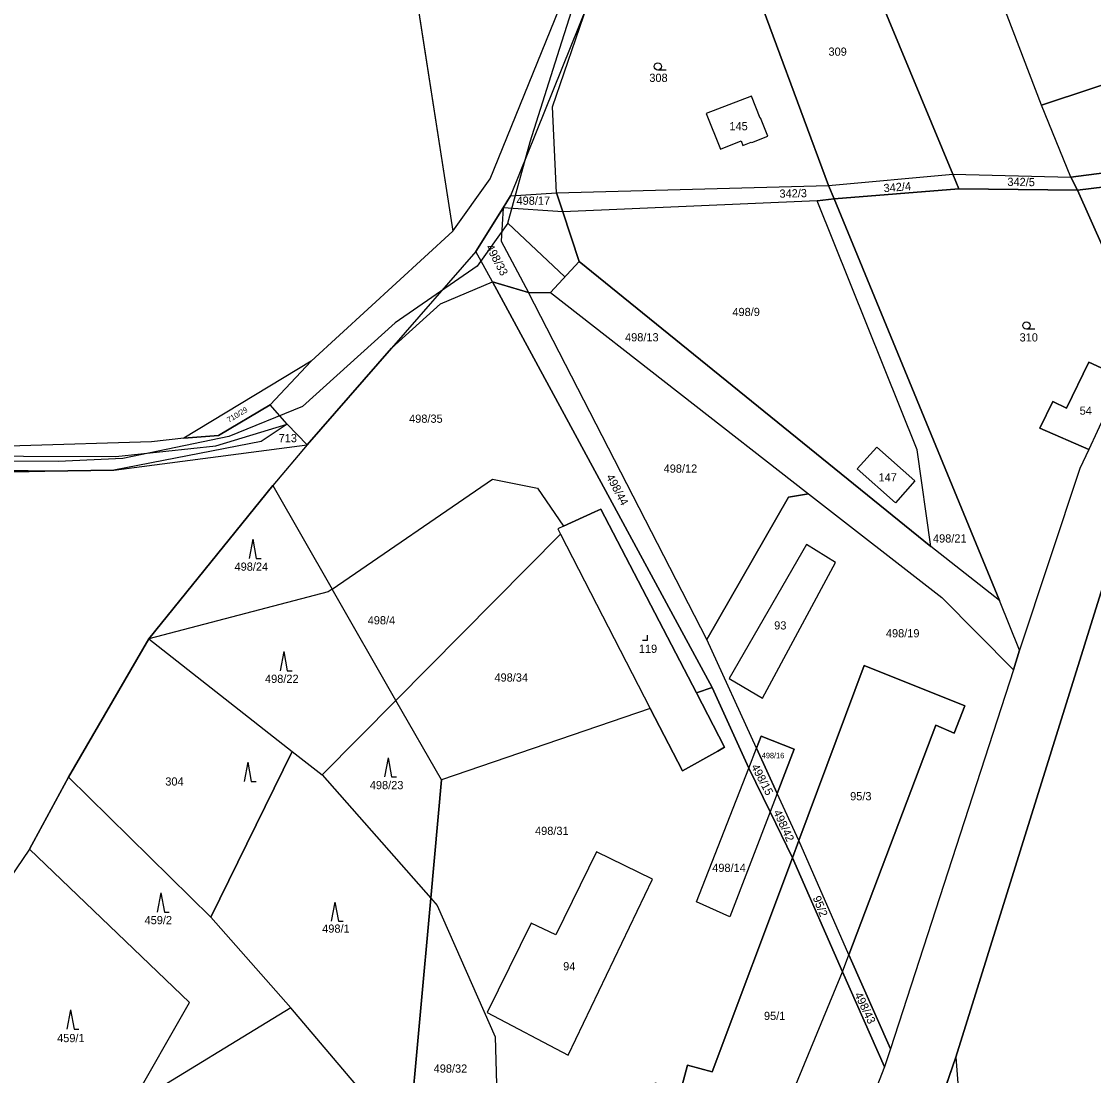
# Model space of a CAD drawing. Extents: x -590606 to -587796, y -1065936 to -1062515.
# Drawn here: x -589413.2 to -589191, y -1064752.6 to -1064534.1 of the extents above; entities that cross this region are included whole.
import ezdxf

# ---------------------------------------------------------------- set-up
doc = ezdxf.new("R2010")
doc.units = 0
for name, color, linetype in [('Cesty', 7, 'Continuous'), ('Parcela nároku', 7, 'Continuous'), ('Vnější obvod_ Studené', 7, 'Continuous'), ('Vrstva 30', 7, 'Continuous')]:
    doc.layers.add(name, color=color, linetype=linetype)

msp = doc.modelspace()

# ---------------------------------------------------------------- linework, layer by layer
at = {"layer": 'Cesty'}
for points in [[(-589300.58, -1064587.06), (-589312.39, -1064575.92), (-589307.76, -1064559.09), (-589301.66, -1064539.86), (-589293.47, -1064514.04), (-589288.03, -1064490.09), (-589285.92, -1064475.12)], [(-589312.39, -1064575.92), (-589318.72, -1064584.83), (-589335.76, -1064596.6), (-589354.95, -1064613.9), (-589370.21, -1064620.11), (-589392.14, -1064624.65), (-589405.6, -1064625.31), (-589467.35, -1064625.2), (-589485.5, -1064624.04), (-589517.23, -1064616.87), (-589543.56, -1064607.17), (-589549.94, -1064607.84), (-589566.34, -1064608.24), (-589595.98, -1064606.38), (-589632.73, -1064602.69), (-589650.77, -1064600.08), (-589699.72, -1064596.26), (-589711.59, -1064596.2), (-589764.62, -1064605.69), (-589799.36, -1064611.91)]]:
    msp.add_lwpolyline(points, dxfattribs=at)
at = {"layer": 'Parcela nároku'}
for points in [[(-589417.38, -1064171.67), (-589379.94, -1064201.41), (-589369.57, -1064272.3), (-589363.57, -1064313.27), (-589352.69, -1064387.69), (-589339.13, -1064479.06), (-589323.75, -1064577.55), (-589353.13, -1064604.54), (-589379.5, -1064620.44), (-589386.23, -1064621.24), (-589413.51, -1064622.05)], [(-589295.88, -1064530.66), (-589311.85, -1064570.25), (-589313.34, -1064572.76), (-589319, -1064581.76), (-589353.94, -1064621.82), (-589358.1, -1064617.56), (-589361.6, -1064613.55), (-589353.13, -1064604.54), (-589323.75, -1064577.55), (-589316.02, -1064566.74), (-589296.44, -1064518.34)], [(-589185.08, -1064607.88), (-589192.01, -1064622.83), (-589193.83, -1064626.75), (-589206.34, -1064664.38), (-589207.6, -1064668.51), (-589233.09, -1064747.06), (-589234.34, -1064750.74), (-589263.43, -1064825.24)], [(-589228.83, -1064775.58), (-589219.53, -1064748.72), (-589186.36, -1064642.57)], [(-589276.55, -1064755.62), (-589275.16, -1064750.39), (-589270.07, -1064751.82), (-589253.42, -1064707.43), (-589258.04, -1064697.93), (-589266.37, -1064719.64), (-589273.27, -1064716.55), (-589262.46, -1064688.85), (-589270.04, -1064672.11), (-589273.31, -1064673.23), (-589267.45, -1064684.51), (-589268.88, -1064685.31), (-589276.21, -1064689.44), (-589282.87, -1064676.49), (-589326.15, -1064691.27), (-589328.36, -1064715.8), (-589327.02, -1064717.33), (-589315.01, -1064744.55), (-589314.53, -1064761.77)]]:
    msp.add_lwpolyline(points, dxfattribs=at)
for points in [[(-589232.4, -1064471.45), (-589208.79, -1064446.47), (-589168.83, -1064517.27), (-589164.65, -1064524.67), (-589161.07, -1064530.98), (-589156.51, -1064536.45), (-589159.83, -1064537.55), (-589201.82, -1064551.44)], [(-589201.82, -1064551.44), (-589232.4, -1064471.45), (-589251.47, -1064490.39), (-589220.15, -1064565.79), (-589195.69, -1064566.38)], [(-589290.65, -1064472.89), (-589339.13, -1064479.06), (-589323.75, -1064577.55), (-589316.02, -1064566.74), (-589296.44, -1064518.34), (-589290.27, -1064497.32), (-589287.86, -1064475.38)], [(-589251.47, -1064490.39), (-589268.87, -1064506.17), (-589245.96, -1064568.09), (-589220.15, -1064565.79)], [(-589245.96, -1064568.09), (-589268.87, -1064506.17), (-589295.88, -1064530.66), (-589311.85, -1064570.25), (-589302.27, -1064569.61)], [(-589201.82, -1064551.44), (-589159.83, -1064537.55), (-589146.1, -1064555.02), (-589143.75, -1064552.4), (-589146.65, -1064555.73), (-589171.28, -1064563.22), (-589195.69, -1064566.38)], [(-589271.26, -1064553.15), (-589268.32, -1064560.56), (-589264.03, -1064558.88), (-589263.66, -1064559.83), (-589261.92, -1064559.12), (-589261.85, -1064559.21), (-589258.52, -1064557.86), (-589259.99, -1064554.08), (-589260.11, -1064554.14), (-589261.9, -1064549.56)], [(-589258.52, -1064557.86), (-589259.99, -1064554.08), (-589260.11, -1064554.14), (-589261.9, -1064549.56), (-589271.26, -1064553.15), (-589268.32, -1064560.56), (-589264.03, -1064558.88), (-589263.66, -1064559.83), (-589261.92, -1064559.12), (-589261.85, -1064559.21)], [(-589171.28, -1064563.22), (-589146.65, -1064555.73), (-589149.4, -1064559.72), (-589171.12, -1064566.23), (-589194.33, -1064569.05), (-589195.69, -1064566.38)], [(-589171.12, -1064566.23), (-589149.4, -1064559.72), (-589167.86, -1064579.14), (-589170.85, -1064576.72), (-589177.93, -1064571.33), (-589181.12, -1064575.26), (-589183.77, -1064573.16), (-589186.71, -1064576.96), (-589184.14, -1064578.99), (-589185.99, -1064581.28), (-589179.04, -1064586.54), (-589174.88, -1064589.8), (-589180.97, -1064599.01), (-589194.33, -1064569.05)], [(-589245.96, -1064568.09), (-589220.15, -1064565.79), (-589218.91, -1064568.78), (-589244.72, -1064570.89)], [(-589220.15, -1064565.79), (-589195.69, -1064566.38), (-589194.33, -1064569.05), (-589218.91, -1064568.78)], [(-589302.27, -1064569.61), (-589300.98, -1064573.57), (-589313.34, -1064572.76), (-589311.85, -1064570.25)], [(-589245.96, -1064568.09), (-589244.72, -1064570.89), (-589248.26, -1064571.29), (-589300.98, -1064573.57), (-589302.27, -1064569.61)], [(-589194.33, -1064569.05), (-589180.97, -1064599.01), (-589185.08, -1064607.88), (-589191.95, -1064604.69), (-589196.61, -1064614.26), (-589199.45, -1064612.86), (-589202.15, -1064618.39), (-589192.01, -1064622.83), (-589193.83, -1064626.75), (-589206.34, -1064664.38), (-589210.5, -1064654.09), (-589244.72, -1064570.89), (-589218.91, -1064568.78)], [(-589248.26, -1064571.29), (-589300.98, -1064573.57), (-589297.58, -1064583.86), (-589224.75, -1064642.9), (-589227.54, -1064622.88)], [(-589244.72, -1064570.89), (-589210.5, -1064654.09), (-589224.75, -1064642.9), (-589227.54, -1064622.88), (-589248.26, -1064571.29)], [(-589319, -1064581.76), (-589313.34, -1064572.76), (-589313.79, -1064579.63), (-589308.1, -1064590.25), (-589315.59, -1064588.05)], [(-589300.98, -1064573.57), (-589313.34, -1064572.76), (-589313.79, -1064579.63), (-589308.1, -1064590.25), (-589303.57, -1064590.25), (-589250.07, -1064631.99), (-589222.47, -1064653.52), (-589207.6, -1064668.51), (-589206.34, -1064664.38), (-589210.5, -1064654.09), (-589224.75, -1064642.9), (-589297.58, -1064583.86)], [(-589315.59, -1064588.05), (-589319, -1064581.76), (-589353.94, -1064621.82), (-589361.07, -1064630.25), (-589348.76, -1064651.76), (-589315.53, -1064628.94), (-589306.24, -1064630.8), (-589300.86, -1064638.73), (-589294.32, -1064635.71), (-589293.1, -1064635.15), (-589273.31, -1064673.23), (-589270.04, -1064672.11)], [(-589308.1, -1064590.25), (-589315.59, -1064588.05), (-589270.04, -1064672.11), (-589262.46, -1064688.85), (-589260.85, -1064684.74), (-589271.17, -1064662.21)], [(-589303.57, -1064590.25), (-589250.07, -1064631.99), (-589254.19, -1064632.69), (-589271.17, -1064662.21), (-589308.1, -1064590.25)], [(-589358.1, -1064617.56), (-589361.6, -1064613.55), (-589372.34, -1064619.94), (-589379.5, -1064620.44), (-589386.23, -1064621.24), (-589413.51, -1064622.05), (-589457.96, -1064622.14), (-589477.97, -1064621.63), (-589499, -1064619.25), (-589523.88, -1064612.81), (-589541.19, -1064604.66), (-589542.09, -1064606.65), (-589525.32, -1064613.43), (-589500.34, -1064620.07), (-589470.25, -1064623.98), (-589393.65, -1064624.26), (-589372.9, -1064622.03)], [(-589353.13, -1064604.54), (-589379.5, -1064620.44), (-589372.34, -1064619.94), (-589361.6, -1064613.55)], [(-589202.15, -1064618.39), (-589199.45, -1064612.86), (-589196.61, -1064614.26), (-589191.95, -1064604.69), (-589185.08, -1064607.88), (-589192.01, -1064622.83)], [(-589393.65, -1064624.26), (-589372.9, -1064622.03), (-589358.1, -1064617.56), (-589363.47, -1064621.18), (-589394.04, -1064627.1), (-589408.35, -1064627.34), (-589467.25, -1064626.15), (-589500.72, -1064621.47), (-589504.92, -1064620.61), (-589508.23, -1064619.91), (-589524.33, -1064616.05), (-589543.01, -1064608.6), (-589542.09, -1064606.65), (-589525.32, -1064613.43), (-589500.34, -1064620.07), (-589470.25, -1064623.98)], [(-589358.1, -1064617.56), (-589363.47, -1064621.18), (-589394.04, -1064627.1), (-589353.94, -1064621.82)], [(-589500.84, -1064624.06), (-589472.75, -1064628.4), (-589408.35, -1064627.34), (-589394.04, -1064627.1), (-589353.94, -1064621.82), (-589361.07, -1064630.25), (-589386.79, -1064662.08), (-589403.44, -1064690.75), (-589411.5, -1064705.67), (-589425, -1064725.38), (-589447.12, -1064755.09), (-589470.54, -1064721.2), (-589496.13, -1064671.82), (-589500.39, -1064655.52), (-589501.22, -1064639.68)], [(-589500.72, -1064621.47), (-589467.25, -1064626.15), (-589408.35, -1064627.34), (-589472.75, -1064628.4), (-589500.84, -1064624.06)], [(-589232.05, -1064633.87), (-589240.02, -1064626.79), (-589235.94, -1064622.3), (-589228.01, -1064629.32)], [(-589235.94, -1064622.3), (-589228.01, -1064629.32), (-589232.05, -1064633.87), (-589240.02, -1064626.79)], [(-589315.53, -1064628.94), (-589306.24, -1064630.8), (-589300.86, -1064638.73), (-589302.01, -1064639.26), (-589301.45, -1064640.36), (-589335.56, -1064674.82), (-589348.76, -1064651.76)], [(-589386.79, -1064662.08), (-589361.07, -1064630.25), (-589348.76, -1064651.76), (-589349.58, -1064652.32)], [(-589222.47, -1064653.52), (-589207.6, -1064668.51), (-589233.09, -1064747.06), (-589241.68, -1064727.54), (-589223.69, -1064679.94), (-589219.9, -1064681.59), (-589217.69, -1064675.93), (-589238.57, -1064667.58), (-589252.09, -1064703.88), (-589256.57, -1064694.1), (-589253.04, -1064684.91), (-589259.88, -1064682.25), (-589260.85, -1064684.74), (-589271.17, -1064662.21), (-589254.19, -1064632.69), (-589250.07, -1064631.99)], [(-589294.32, -1064635.71), (-589300.86, -1064638.73), (-589302.01, -1064639.26), (-589301.45, -1064640.36), (-589282.87, -1064676.49), (-589276.21, -1064689.44), (-589268.88, -1064685.31), (-589267.45, -1064684.51), (-589273.31, -1064673.23), (-589293.1, -1064635.15)], [(-589301.45, -1064640.36), (-589282.87, -1064676.49), (-589326.15, -1064691.27), (-589335.56, -1064674.82)], [(-589250.46, -1064642.52), (-589266.51, -1064670.27), (-589259.59, -1064674.34), (-589244.49, -1064646.21)], [(-589266.51, -1064670.27), (-589259.59, -1064674.34), (-589244.49, -1064646.21), (-589250.46, -1064642.52)], [(-589123.59, -1064757.72), (-589141.72, -1064723.62), (-589157.85, -1064685.09), (-589185.23, -1064641.99), (-589186.36, -1064642.57), (-589219.53, -1064748.72), (-589218.27, -1064765.02), (-589213.92, -1064786.57), (-589188.45, -1064839.84), (-589159.82, -1064824.9), (-589138.93, -1064817.47), (-589090.35, -1064802), (-589107.58, -1064783.08)], [(-589335.56, -1064674.82), (-589348.76, -1064651.76), (-589349.58, -1064652.32), (-589386.79, -1064662.08), (-589357.1, -1064685.38), (-589350.86, -1064690.27)], [(-589403.44, -1064690.75), (-589386.79, -1064662.08), (-589357.1, -1064685.38), (-589373.96, -1064719.72)], [(-589252.09, -1064703.88), (-589238.57, -1064667.58), (-589217.69, -1064675.93), (-589219.9, -1064681.59), (-589223.69, -1064679.94), (-589241.68, -1064727.54)], [(-589326.15, -1064691.27), (-589335.56, -1064674.82), (-589350.86, -1064690.27), (-589328.36, -1064715.8)], [(-589259.88, -1064682.25), (-589253.04, -1064684.91), (-589256.57, -1064694.1), (-589260.85, -1064684.74)], [(-589262.46, -1064688.85), (-589260.85, -1064684.74), (-589256.57, -1064694.1), (-589258.04, -1064697.93)], [(-589350.86, -1064690.27), (-589328.36, -1064715.8), (-589332.88, -1064765.85), (-589343.1, -1064755.32), (-589357.37, -1064738.5), (-589373.96, -1064719.72), (-589357.1, -1064685.38)], [(-589273.27, -1064716.55), (-589262.46, -1064688.85), (-589258.04, -1064697.93), (-589266.37, -1064719.64)], [(-589390.57, -1064758.82), (-589378.38, -1064737.45), (-589411.5, -1064705.67), (-589403.44, -1064690.75), (-589373.96, -1064719.72), (-589357.37, -1064738.5)], [(-589256.57, -1064694.1), (-589258.04, -1064697.93), (-589253.42, -1064707.43), (-589252.09, -1064703.88)], [(-589252.09, -1064703.88), (-589253.42, -1064707.43), (-589243.01, -1064731.06), (-589241.68, -1064727.54)], [(-589378.38, -1064737.45), (-589411.5, -1064705.67), (-589425, -1064725.38), (-589416.09, -1064747.85), (-589424.1, -1064799.94), (-589411.31, -1064785.43), (-589390.57, -1064758.82)], [(-589294.02, -1064706.18), (-589302.43, -1064723.43), (-589307.54, -1064720.99), (-589316.68, -1064739.48), (-589299.85, -1064748.31), (-589282.43, -1064711.84)], [(-589316.68, -1064739.48), (-589299.85, -1064748.31), (-589282.43, -1064711.84), (-589294.02, -1064706.18), (-589302.43, -1064723.43), (-589307.54, -1064720.99)], [(-589253.42, -1064707.43), (-589270.07, -1064751.82), (-589275.16, -1064750.39), (-589276.55, -1064755.62), (-589281.83, -1064754.11), (-589283.17, -1064759.09), (-589275.55, -1064761.71), (-589277.01, -1064764.94), (-589266.51, -1064770.69), (-589260.6, -1064773.58), (-589243.01, -1064731.06)], [(-589328.36, -1064715.8), (-589327.02, -1064717.33), (-589315.01, -1064744.55), (-589314.53, -1064761.77), (-589322.47, -1064774.76), (-589332.88, -1064765.85)], [(-589241.68, -1064727.54), (-589233.09, -1064747.06), (-589234.34, -1064750.74), (-589243.01, -1064731.06)], [(-589280.35, -1064796.2), (-589266.51, -1064770.69), (-589260.6, -1064773.58), (-589243.01, -1064731.06), (-589234.34, -1064750.74), (-589263.43, -1064825.24), (-589280.83, -1064810.36), (-589274.81, -1064799.22)], [(-589357.37, -1064738.5), (-589390.57, -1064758.82), (-589364.57, -1064781.21), (-589351.34, -1064765.42), (-589343.1, -1064755.32)], [(-589218.27, -1064765.02), (-589213.92, -1064786.57), (-589188.45, -1064839.84), (-589186.9, -1064843.85), (-589160.9, -1064918.18), (-589148.42, -1064969.62), (-589144.75, -1065009.02), (-589145.9, -1065034.24), (-589156.15, -1065074.53), (-589176.99, -1065132.2), (-589180.29, -1065141.18), (-589191.9, -1065194.84), (-589196.32, -1065193.25), (-589184.2, -1065137.36), (-589161.34, -1065072.9), (-589151.23, -1065033.97), (-589150.92, -1065007.3), (-589154.33, -1064973.17), (-589164.98, -1064928.86), (-589195.94, -1064838.44), (-589220.02, -1064787.63), (-589228.83, -1064775.58), (-589219.53, -1064748.72)]]:
    msp.add_lwpolyline(points, close=True, dxfattribs=at)
at = {"layer": 'Vnější obvod_ Studené'}
for p, q in [((-589339.13, -1064479.06), (-589323.75, -1064577.55)), ((-589303.1, -1064551.82), (-589295.88, -1064530.66)), ((-589302.27, -1064569.61), (-589303.1, -1064551.82)), ((-589300.98, -1064573.57), (-589302.27, -1064569.61)), ((-589297.58, -1064583.86), (-589300.98, -1064573.57)), ((-589323.75, -1064577.55), (-589353.13, -1064604.54)), ((-589303.57, -1064590.25), (-589297.58, -1064583.86)), ((-589326.31, -1064592.65), (-589315.59, -1064588.05)), ((-589315.59, -1064588.05), (-589308.1, -1064590.25)), ((-589308.1, -1064590.25), (-589303.57, -1064590.25)), ((-589336.47, -1064601.79), (-589326.31, -1064592.65)), ((-589353.94, -1064621.82), (-589336.47, -1064601.79)), ((-589353.13, -1064604.54), (-589379.5, -1064620.44)), ((-589379.5, -1064620.44), (-589386.23, -1064621.24)), ((-589386.23, -1064621.24), (-589413.51, -1064622.05)), ((-589394.04, -1064627.1), (-589353.94, -1064621.82)), ((-589472.75, -1064628.4), (-589408.35, -1064627.34)), ((-589408.35, -1064627.34), (-589394.04, -1064627.1)), ((-589186.36, -1064642.57), (-589202.94, -1064695.64)), ((-589202.94, -1064695.64), (-589219.53, -1064748.72)), ((-589219.53, -1064748.72), (-589228.83, -1064775.58))]:
    msp.add_line(p, q, dxfattribs=at)
at = {"layer": 'Vrstva 30'}
for p, q in [((-589279.54, -1064544.18), (-589281.29, -1064544.18)), ((-589203.17, -1064597.86), (-589204.92, -1064597.86)), ((-589365.24, -1064641.41), (-589365.97, -1064645.41)), ((-589365.24, -1064641.41), (-589364.51, -1064645.41)), ((-589364.51, -1064645.41), (-589363.51, -1064645.41)), ((-589358.81, -1064664.66), (-589359.55, -1064668.66)), ((-589358.81, -1064664.66), (-589358.08, -1064668.66)), ((-589358.08, -1064668.66), (-589357.08, -1064668.66)), ((-589337.2, -1064686.69), (-589337.94, -1064690.69)), ((-589337.2, -1064686.69), (-589336.47, -1064690.69)), ((-589366.28, -1064687.59), (-589367.02, -1064691.59)), ((-589366.28, -1064687.59), (-589365.55, -1064691.59)), ((-589365.55, -1064691.59), (-589364.55, -1064691.59)), ((-589336.47, -1064690.69), (-589335.47, -1064690.69)), ((-589384.28, -1064714.71), (-589385.02, -1064718.71)), ((-589384.28, -1064714.71), (-589383.55, -1064718.71)), ((-589348.23, -1064716.6), (-589348.96, -1064720.6)), ((-589348.23, -1064716.6), (-589347.5, -1064720.6)), ((-589383.55, -1064718.71), (-589382.55, -1064718.71)), ((-589347.5, -1064720.6), (-589346.5, -1064720.6)), ((-589403.01, -1064738.97), (-589403.74, -1064742.97)), ((-589403.01, -1064738.97), (-589402.28, -1064742.97)), ((-589402.28, -1064742.97), (-589401.28, -1064742.97))]:
    msp.add_line(p, q, dxfattribs=at)
msp.add_lwpolyline([(-589284.46, -1064662.31), (-589283.46, -1064662.31), (-589283.46, -1064661.31)], dxfattribs=at)
for centre in [(-589281.29, -1064543.43), (-589204.92, -1064597.11)]:
    msp.add_circle(centre, 0.75, dxfattribs=at)

# ---------------------------------------------------------------- texts
at = {"layer": 'Parcela nároku'}
for s, height, p in [('309', 1.7, (-589245.93, -1064541.21)), ('308', 1.7, (-589283.06, -1064546.64)), ('145', 1.7, (-589266.46, -1064556.66)), ('498/17', 1.7, (-589310.58, -1064572.1)), ('498/9', 1.7, (-589265.84, -1064595.16)), ('498/13', 1.7, (-589288.09, -1064600.41)), ('310', 1.7, (-589206.33, -1064600.43)), ('54', 1.7, (-589193.88, -1064615.61)), ('498/35', 1.7, (-589332.84, -1064617.28)), ('713', 1.7, (-589359.88, -1064621.31)), ('498/12', 1.7, (-589280.09, -1064627.62)), ('147', 1.7, (-589235.56, -1064629.44)), ('498/21', 1.7, (-589224.27, -1064642.1)), ('498/24', 1.7, (-589369.01, -1064647.94)), ('498/4', 1.7, (-589341.42, -1064659.06)), ('93', 1.7, (-589257.18, -1064660.12)), ('498/19', 1.7, (-589234.03, -1064661.75)), ('119', 1.7, (-589285.23, -1064664.96)), ('498/22', 1.7, (-589362.7, -1064671.19)), ('498/34', 1.7, (-589315.15, -1064670.92)), ('498/16', 1.14, (-589259.76, -1064686.81)), ('304', 1.7, (-589383.37, -1064692.47)), ('498/23', 1.7, (-589340.98, -1064693.22)), ('95/3', 1.7, (-589241.44, -1064695.52)), ('498/31', 1.7, (-589306.74, -1064702.7)), ('498/14', 1.7, (-589270.02, -1064710.36)), ('459/2', 1.7, (-589387.66, -1064721.2)), ('498/1', 1.7, (-589350.85, -1064722.96)), ('94', 1.7, (-589300.91, -1064730.77)), ('95/1', 1.7, (-589259.3, -1064741.05)), ('459/1', 1.7, (-589405.78, -1064745.64)), ('498/32', 1.7, (-589327.75, -1064751.96))]:
    msp.add_text(s, height=height, dxfattribs=at).set_placement(p)
for s, height, rotation, p in [('342/4', 1.7, 4.6736, (-589234.44, -1064569.51)), ('342/5', 1.7, 359.3706, (-589208.86, -1064568.19)), ('342/3', 1.7, 1.1432, (-589256.07, -1064570.64)), ('498/33', 1.7, 297.8, (-589316.99, -1064580.85)), ('710/29', 1.14, 30.8482, (-589370.17, -1064617.29)), ('498/44', 1.7, 297.8, (-589292.04, -1064628.47)), ('498/15', 1.7, 297.7884, (-589262.02, -1064688.54)), ('498/42', 1.7, 294.6065, (-589257.4, -1064697.96)), ('95/2', 1.7, 291.5382, (-589249.23, -1064715.72)), ('498/43', 1.7, 295.4681, (-589240.6, -1064735.77))]:
    msp.add_text(s, height=height, rotation=rotation, dxfattribs=at).set_placement(p)

doc.saveas('drawing.dxf')
